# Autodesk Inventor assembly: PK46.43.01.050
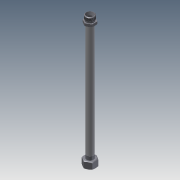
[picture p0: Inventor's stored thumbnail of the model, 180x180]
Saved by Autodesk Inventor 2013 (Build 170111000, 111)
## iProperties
Shininess: 64.0
Length Units: 11269
Angle Units: 11279
Time Units: 11290
Mass Units: 11283
Length Display Precision: 3
Angle Display Precision: 2
Compacted: True
Created: 2004-12
Part Number: PK46.43.01.050
Document SubType Name: Assembly
Designer: ELarisa
Manufacturer: Standard
Standards Organization: Custom
Density: 0.0
Volumn: 0.0
Area: 0.0
PropertySet Name: Model Information
Control State: 0
Master: False
Checked Out: False
Checked Out Date: 2008-10-09
Last Check In Date: 2008-10-09
Author: ELarisa
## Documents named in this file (5)
- D:\FrontLoaderVault\Data\Assy, Chassis, Front\PK46.43.01.050.iam
- D:\FrontLoaderVault\Data\Assy, Chassis, Front\PK46.43.01.017.ipt
- D:\FrontLoaderVault\Data\Assy, Chassis, Front\027.03.04.034.ipt
- D:\FrontLoaderVault\Data\Assy, Chassis, Front\027.08.00.004.ipt
- D:\FrontLoaderVault\Data\Assy, Chassis, Front\027.07.03.005.ipt
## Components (4 placed, 4 different names)
1. PK46.43.01.017:1 — Insert:4
2. 027.08.00.004:1 — Insert:3
3. 027.07.03.005:1 — Insert:3
4. 027.03.04.034:1 — Insert:4
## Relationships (2: Insert 2)
- Insert:3: 027.08.00.004:1 ↔ 027.07.03.005:1
- Insert:4: PK46.43.01.017:1 ↔ 027.03.04.034:1
